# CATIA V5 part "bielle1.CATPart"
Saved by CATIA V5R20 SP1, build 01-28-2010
Part number: Part1.1
Bounding box of the stored display mesh (mm): x 13 to 87, y -5 to 10, z 28.093 to 41.907
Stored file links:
  E:\EDELI\gcausse\Edeli_2012_686_gcausse\bielle1.CATPart
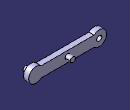
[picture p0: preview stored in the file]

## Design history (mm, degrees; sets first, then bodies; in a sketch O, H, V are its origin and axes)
Parameters
  long = 0.06
  diamtrou = 0.005
Body1 (main body)
  Sketch1 on zx-plane, origin (0, 0, 0), H (-1, 0, 0), V (0, 0, 1)
    line L1 (-24.899, 40) -> (-75.101, 40)
    line L2 (-24.899, 30) -> (-75.101, 30)
    arc A1 centre (-20, 35) radius 7 from (-24.899, 40) to (-24.899, 30) cw
    point P5 (-20, 35)
    point P6 (-15.101, 30)
    arc A2 centre (-80, 35) radius 7 from (-75.101, 40) to (-75.101, 30) ccw
    point P7 (-80, 35)
    circle A3 centre (-20, 35) radius 2.5
    distance P7 L1 = 5
    distance P5 L2 = 5
    distance L2 L1 = 10
    radius A1 = 7
    radius A2 = 7
    distance P5 P7 = 60 {= long}
    radius A3 = 2.5
    horizontal: L1 H, L2 H
    coincidence: A1 P6, P6 L2
  Pad1: profile Sketch1, direction (0, 1, 0), length 5
  Sketch2 on end face of Pad1, origin (0, 5, 0), H (-1, 0, 0), V (0, 0, 1)
    circle A1 centre (-80, 35) radius 2.5
    reference projected arc E1 centre (-80, 35) radius 7 from (-75.101, 40) to (-75.101, 30) ccw from edge [face of Pad1 from Sketch1.A2 | end face of Pad1]
    reference projected arc E2 centre (-80, 35) radius 7 from (-75.101, 40) to (-75.101, 30) ccw from edge [face of Pad1 from Sketch1.A2 | end face of Pad1]
    radius A1 = 2.5
    radius E2 = 7 (reference)
    concentricity: A1 E1
  Pad2: profile Sketch2, direction (0, -1, 0), length 10
  DatumSurface1
  Sketch3 on end face of Pad1, origin (0, 5, 0), H (-1, 0, 0), V (0, 0, 1)
    circle A1 centre (-50, 35) radius 2.5
    point P1 (-50, 35)
    reference projected line E1 (-75.101, 30) -> (-24.899, 30) from edge [face of Pad1 from Sketch1.L2 | end face of Pad1]
    reference projected line E2 (-24.899, 40) -> (-75.101, 40) from edge [face of Pad1 from Sketch1.L1 | end face of Pad1]
    reference projected point E3 (-20, 35) from axis of face of Pad1 from Sketch1.A3
    reference projected point E4 (-80, 35) from axis of face of Pad2 from Sketch2.A1
    radius A1 = 2.5
    equidistance: E1 E2 P1, E3 E4 P1
  Pad3: profile Sketch3, direction (0, 1, 0), length 5
  Sketch4 on face of DatumSurface1, origin (0, 25, 0), H (1, 0, 0), V (0, 0, 1)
